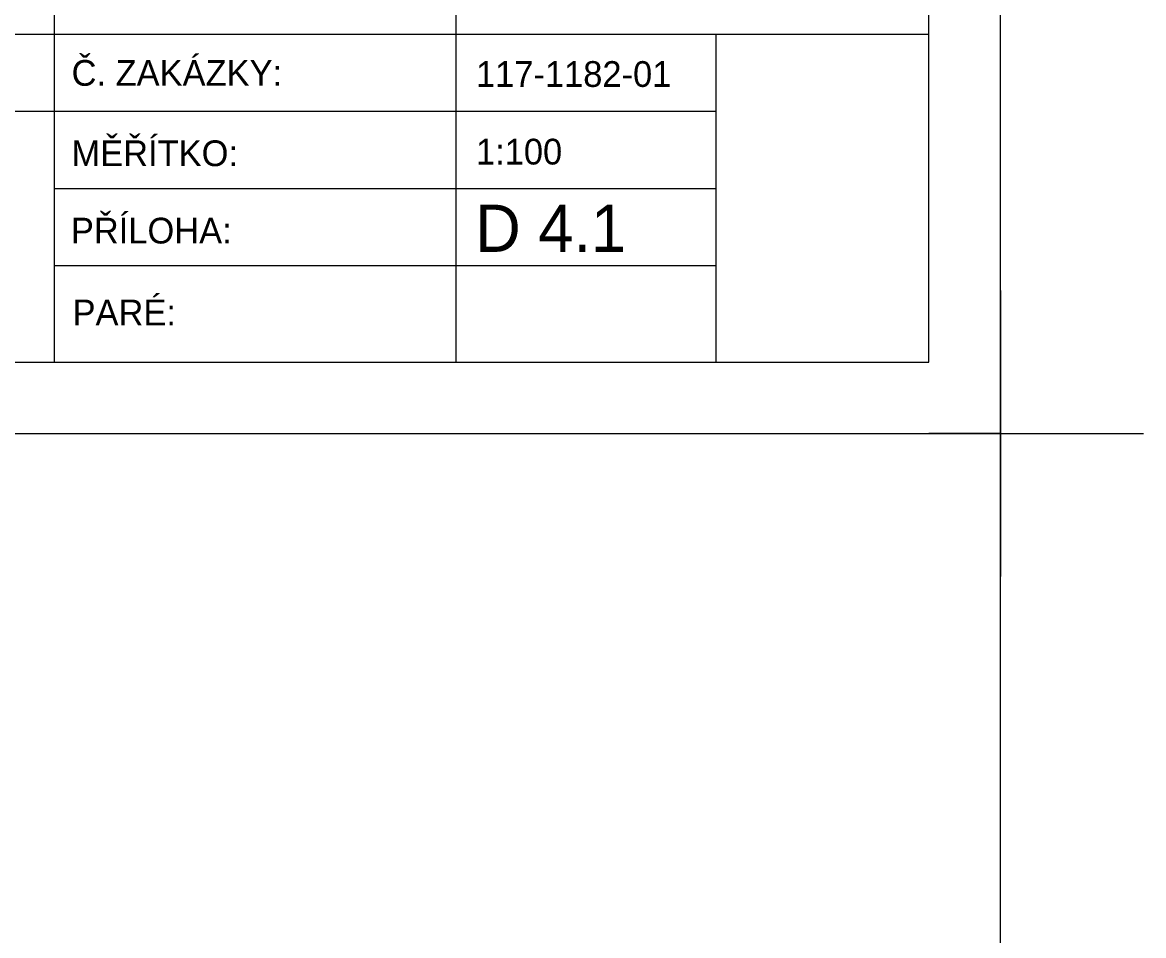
# Model space of a CAD drawing. Extents: x -552501 to -552394, y -1029983 to -1029892.
# Drawn here: x -552401.59 to -552393.76, y -1029926.56 to -1029920.18 of the extents above; entities that cross this region are included whole.
import ezdxf

# ---------------------------------------------------------------- set-up
doc = ezdxf.new("R2010")
doc.units = 0
doc.layers.add('FORMATY', color=7, linetype='Continuous')
doc.layers.add('rámeček', color=7, linetype='Continuous')

msp = doc.modelspace()

# ---------------------------------------------------------------- linework, layer by layer
at = {"layer": 'FORMATY'}
for p, q in [((-552394.7555, -1029922.0502), (-552394.7555, -1029924.0502)), ((-552395.7555, -1029923.0502), (-552393.7555, -1029923.0502))]:
    msp.add_line(p, q, dxfattribs=at)
at = {"layer": 'rámeček'}
for p, q in [((-552394.7555, -1029923.0502), (-552394.7555, -1029893.3502)), ((-552394.7555, -1029923.0502), (-552394.7555, -1029893.3502)), ((-552401.3656, -1029922.5502), (-552401.3656, -1029916.3951)), ((-552395.2555, -1029922.5502), (-552395.2555, -1029916.3951)), ((-552398.5584, -1029922.5502), (-552398.5584, -1029918.1023)), ((-552410.7555, -1029920.2588), (-552395.2555, -1029920.2588)), ((-552396.7451, -1029920.2588), (-552396.7451, -1029922.5502)), ((-552410.7555, -1029920.798), (-552396.7451, -1029920.798)), ((-552401.3656, -1029921.3371), (-552396.7451, -1029921.3369)), ((-552401.3656, -1029921.8762), (-552396.7451, -1029921.8762)), ((-552410.7555, -1029922.5502), (-552395.2555, -1029922.5502)), ((-552394.7555, -1029922.5502), (-552394.7555, -1029923.0502)), ((-552394.7555, -1029923.0502), (-552394.7555, -1029922.5502)), ((-552499.7555, -1029923.0502), (-552394.7555, -1029923.0502)), ((-552499.7555, -1029923.0502), (-552394.7555, -1029923.0502)), ((-552499.7555, -1029923.0502), (-552394.7555, -1029923.0502)), ((-552394.7555, -1029923.0502), (-552395.2555, -1029923.0502)), ((-552395.2555, -1029923.0502), (-552394.7555, -1029923.0502)), ((-552395.2555, -1029923.0502), (-552394.7555, -1029923.0502)), ((-552394.7555, -1029952.7502), (-552394.7555, -1029923.0502)), ((-552394.7555, -1029952.7502), (-552394.7555, -1029923.0502))]:
    msp.add_line(p, q, dxfattribs=at)

# ---------------------------------------------------------------- texts
for s, height, p in [('Č. ZAKÁZKY:', 0.18, (-552401.2456, -1029920.6198)), ('117-1182-01', 0.18, (-552398.42, -1029920.6277)), ('MĚŘÍTKO:', 0.18, (-552401.2462, -1029921.1814)), ('1:100', 0.18, (-552398.42, -1029921.17)), ('D 4.1', 0.33, (-552398.4259, -1029921.7806)), ('PŘÍLOHA:', 0.18, (-552401.2504, -1029921.722)), ('PARÉ:', 0.18, (-552401.2388, -1029922.2943))]:
    msp.add_text(s, height=height, rotation=0, dxfattribs=at).set_placement(p)

doc.saveas('drawing.dxf')
